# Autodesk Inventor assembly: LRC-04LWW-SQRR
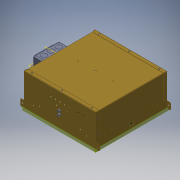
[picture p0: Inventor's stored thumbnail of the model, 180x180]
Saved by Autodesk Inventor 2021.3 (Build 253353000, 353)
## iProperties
Part Number: LRC-04LWW-SQRR
Document SubType Name: Assembly
Designer: JChurch
Author: JChurch
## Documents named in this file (5)
- X:\Revit Files\0000-Un-Zipped\COB\LRC-04LWW-SQR\LRC-04LWW-SQRR.iam
- X:\INVENTOR\830\830557-00-00.iam
- X:\INVENTOR\881\881088-00-00.iam
- X:\INVENTOR\750\750477-00-XX.iam
- X:\INVENTOR\725\725278-01-00.ipt
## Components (4 placed, 4 different names)
1. 830557-00-00:1 [sub-assembly] — Mate:1, Mate:2, Mate:3, Tangent:1, Mate:4, Angle:1, Mate:5
2. 881088-00-00:1 [sub-assembly] — Tangent:1, Mate:4, Angle:1
3. 750477-00-XX:1 [sub-assembly] — Mate:5, Mate:6, Flush:1, Flush:8, Mate:7, Mate:8
4. 725278-01-00:1 — Flush:8, Mate:7, Mate:8
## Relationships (12: Mate 8, Flush 2, Tangent 1, Angle 1)
- Mate:1: 830557-00-00:1
- Mate:2: 830557-00-00:1
- Mate:3: 830557-00-00:1
- Tangent:1: 830557-00-00:1 ↔ 881088-00-00:1
- Mate:4: 830557-00-00:1 ↔ 881088-00-00:1
- Angle:1: 830557-00-00:1 ↔ 881088-00-00:1
- Mate:5: 830557-00-00:1 ↔ 750477-00-XX:1
- Mate:6: 750477-00-XX:1
- Flush:1: 750477-00-XX:1
- Flush:8: 750477-00-XX:1 ↔ 725278-01-00:1
- Mate:7: 750477-00-XX:1 ↔ 725278-01-00:1
- Mate:8: 750477-00-XX:1 ↔ 725278-01-00:1
